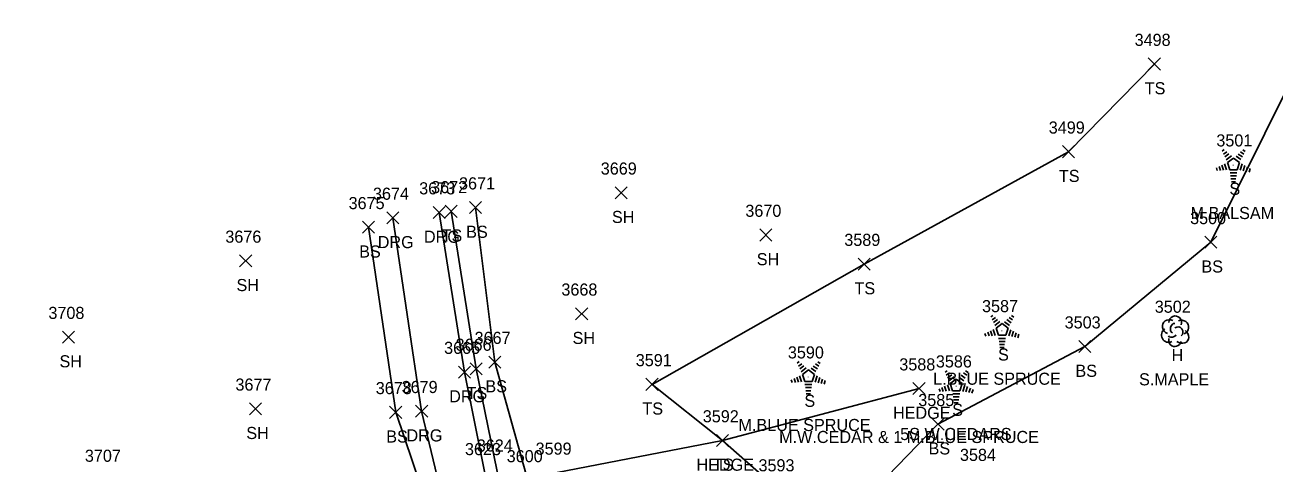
# Model space of a CAD drawing. Extents: x 1520648 to 1523413, y 732854 to 735518.
# Drawn here: x 1521334.6 to 1521541.1, y 733676.1 to 733748.5 of the extents above; entities that cross this region are included whole.
import ezdxf

# ---------------------------------------------------------------- set-up
doc = ezdxf.new("R2010")
doc.units = 0
for name, color, linetype in [('L_A', 7, 'Continuous'), ('L_C', 7, 'Continuous'), ('L_I', 7, 'Continuous'), ('L_TIC', 7, 'Continuous'), ('LAHR', 7, 'Continuous'), ('LELB', 7, 'Continuous'), ('LTC', 7, 'Continuous'), ('LTD', 7, 'Continuous'), ('R_A', 7, 'Continuous'), ('R_I', 7, 'Continuous'), ('R_TIC', 7, 'Continuous'), ('RDG', 7, 'Continuous')]:
    doc.layers.add(name, color=color, linetype=linetype)

msp = doc.modelspace()

# ---------------------------------------------------------------- linework, layer by layer
at = {"layer": 'L_TIC'}
for points in [[(1521520.34, 733741.06), (1521522.34, 733743.06)], [(1521522.34, 733741.06), (1521520.34, 733743.06)], [(1521506.15, 733726.57), (1521508.15, 733728.57)], [(1521508.15, 733726.57), (1521506.15, 733728.57)], [(1521432.17, 733719.79), (1521434.17, 733721.79)], [(1521434.17, 733719.79), (1521432.17, 733721.79)], [(1521404.08, 733716.72), (1521406.08, 733718.72)], [(1521406.08, 733716.72), (1521404.08, 733718.72)], [(1521408.12, 733717.34), (1521410.12, 733719.34)], [(1521410.12, 733717.34), (1521408.12, 733719.34)], [(1521390.43, 733714.08), (1521392.43, 733716.08)], [(1521392.43, 733714.08), (1521390.43, 733716.08)], [(1521456.11, 733712.81), (1521458.11, 733714.81)], [(1521458.11, 733712.81), (1521456.11, 733714.81)], [(1521529.67, 733711.6), (1521531.67, 733713.6)], [(1521531.67, 733711.6), (1521529.67, 733713.6)], [(1521370.11, 733708.53), (1521372.11, 733710.53)], [(1521372.11, 733708.53), (1521370.11, 733710.53)], [(1521472.35, 733708), (1521474.35, 733710)], [(1521474.35, 733708), (1521472.35, 733710)], [(1521425.66, 733699.79), (1521427.66, 733701.79)], [(1521427.66, 733699.79), (1521425.66, 733701.79)], [(1521340.83, 733695.93), (1521342.83, 733697.93)], [(1521342.83, 733695.93), (1521340.83, 733697.93)], [(1521508.85, 733694.36), (1521510.85, 733696.36)], [(1521510.85, 733694.36), (1521508.85, 733696.36)], [(1521408.22, 733690.67), (1521410.22, 733692.67)], [(1521410.22, 733690.67), (1521408.22, 733692.67)], [(1521411.3, 733691.8), (1521413.3, 733693.8)], [(1521413.3, 733691.8), (1521411.3, 733693.8)], [(1521437.29, 733688.12), (1521439.29, 733690.12)], [(1521439.29, 733688.12), (1521437.29, 733690.12)], [(1521481.43, 733687.42), (1521483.43, 733689.42)], [(1521483.43, 733687.42), (1521481.43, 733689.42)], [(1521371.72, 733684.08), (1521373.72, 733686.08)], [(1521373.72, 733684.08), (1521371.72, 733686.08)], [(1521394.91, 733683.5), (1521396.91, 733685.5)], [(1521396.91, 733683.5), (1521394.91, 733685.5)], [(1521484.57, 733681.53), (1521486.57, 733683.53)], [(1521486.57, 733681.53), (1521484.57, 733683.53)], [(1521448.94, 733678.84), (1521450.94, 733680.84)], [(1521450.94, 733678.84), (1521448.94, 733680.84)], [(1521448.94, 733678.84), (1521450.94, 733680.84)], [(1521450.94, 733678.84), (1521448.94, 733680.84)]]:
    msp.add_lwpolyline(points, dxfattribs=at)
at = {"layer": 'LAHR'}
msp.add_lwpolyline([(1521482.43, 733688.42), (1521449.94, 733679.84), (1521422.31, 733674.49)], dxfattribs=at)
at = {"layer": 'LELB'}
for points in [[(1521548.54, 733748.52), (1521530.67, 733712.6), (1521509.85, 733695.36), (1521485.57, 733682.53), (1521468.85, 733665.31), (1521458.55, 733648.55), (1521439.32, 733651.51), (1521417.73, 733673.25), (1521424.64, 733645.07), (1521433.28, 733636.36), (1521449.81, 733635.44), (1521465.25, 733627.96)], [(1521521.34, 733742.06), (1521507.15, 733727.57), (1521473.35, 733709), (1521438.29, 733689.12), (1521449.94, 733679.84), (1521459.15, 733671.74), (1521452.37, 733657.49), (1521440.03, 733660.34), (1521422.31, 733674.49)], [(1521685.16, 733676.19), (1521649.35, 733666.1), (1521610.03, 733655.91), (1521560.37, 733642.72), (1521505.12, 733628.18), (1521444.07, 733615.08), (1521437.41, 733615.5), (1521435.25, 733618.63), (1521426.81, 733622.91), (1521422.63, 733630.43), (1521418.08, 733649.02), (1521412.62, 733675.01), (1521409.22, 733691.67), (1521405.08, 733717.72)], [(1521417.73, 733673.25), (1521412.3, 733692.8), (1521409.12, 733718.34)], [(1521391.43, 733715.08), (1521395.91, 733684.5), (1521401.54, 733667.87), (1521402.17, 733661.87), (1521404.53, 733642.09), (1521399.77, 733626.22), (1521393.85, 733615.3), (1521389.77, 733604.49), (1521375.57, 733598.87), (1521346.27, 733591.74), (1521295.03, 733576.88), (1521253.17, 733566.96), (1521225.68, 733561.04), (1521193.61, 733550.49), (1521146.45, 733540.58), (1521095.03, 733527.62), (1521049.04, 733515.84), (1521035.57, 733513.93), (1521028.78, 733520.1), (1521023.54, 733528.05)]]:
    msp.add_lwpolyline(points, dxfattribs=at)
at = {"layer": 'LTC'}
for p, q in [((1521532.56, 733727.65), (1521532.91, 733727.91)), ((1521532.77, 733727.18), (1521533.3, 733727.57)), ((1521532.98, 733726.72), (1521533.68, 733727.23)), ((1521535.22, 733727.19), (1521535.9, 733726.7)), ((1521535.59, 733727.54), (1521536.14, 733727.14)), ((1521535.96, 733727.89), (1521536.38, 733727.59)), ((1521531.59, 733724.93), (1521531.74, 733724.46)), ((1521532.05, 733725.15), (1521532.26, 733724.49)), ((1521532.5, 733725.36), (1521532.77, 733724.53)), ((1521532.96, 733725.58), (1521533.29, 733724.56)), ((1521533.19, 733726.25), (1521534.07, 733726.89)), ((1521533.41, 733725.8), (1521534.43, 733726.53)), ((1521533.41, 733725.8), (1521533.8, 733724.6)), ((1521534.43, 733726.53), (1521535.42, 733725.81)), ((1521534.85, 733726.85), (1521535.65, 733726.26)), ((1521535.42, 733725.81), (1521535.03, 733724.6)), ((1521535.86, 733725.54), (1521535.52, 733724.5)), ((1521536.3, 733725.29), (1521536.02, 733724.4)), ((1521536.75, 733725.04), (1521536.51, 733724.31)), ((1521535.03, 733724.6), (1521533.8, 733724.6)), ((1521534.99, 733724.1), (1521533.85, 733724.1)), ((1521534.91, 733723.6), (1521533.92, 733723.6)), ((1521534.83, 733723.1), (1521533.99, 733723.1)), ((1521537.19, 733724.79), (1521537.01, 733724.21)), ((1521534.74, 733722.6), (1521534.07, 733722.6)), ((1521494.31, 733700.26), (1521494.66, 733700.52)), ((1521494.52, 733699.8), (1521495.05, 733700.18)), ((1521497.33, 733700.15), (1521497.88, 733699.76)), ((1521497.71, 733700.5), (1521498.13, 733700.2)), ((1521494.71, 733698.19), (1521495.04, 733697.17)), ((1521494.73, 733699.33), (1521495.43, 733699.84)), ((1521494.94, 733698.87), (1521495.81, 733699.5)), ((1521495.16, 733698.41), (1521496.17, 733699.15)), ((1521495.16, 733698.41), (1521495.55, 733697.22)), ((1521496.17, 733699.15), (1521497.17, 733698.42)), ((1521496.59, 733699.46), (1521497.4, 733698.87)), ((1521497.17, 733698.42), (1521496.78, 733697.22)), ((1521496.96, 733699.81), (1521497.64, 733699.31)), ((1521497.61, 733698.15), (1521497.27, 733697.11)), ((1521493.34, 733697.54), (1521493.49, 733697.07)), ((1521493.8, 733697.76), (1521494.01, 733697.11)), ((1521494.25, 733697.98), (1521494.52, 733697.14)), ((1521496.78, 733697.22), (1521495.55, 733697.22)), ((1521496.74, 733696.72), (1521495.6, 733696.72)), ((1521496.66, 733696.22), (1521495.67, 733696.22)), ((1521498.05, 733697.9), (1521497.76, 733697.01)), ((1521498.5, 733697.65), (1521498.26, 733696.92)), ((1521498.94, 733697.4), (1521498.75, 733696.82)), ((1521496.57, 733695.72), (1521495.74, 733695.72)), ((1521496.49, 733695.22), (1521495.81, 733695.22)), ((1521462.29, 733692.61), (1521462.64, 733692.87)), ((1521462.5, 733692.15), (1521463.03, 733692.53)), ((1521462.71, 733691.68), (1521463.41, 733692.19)), ((1521464.95, 733692.15), (1521465.63, 733691.66)), ((1521465.32, 733692.5), (1521465.87, 733692.1)), ((1521465.69, 733692.85), (1521466.11, 733692.55)), ((1521461.32, 733689.89), (1521461.47, 733689.42)), ((1521461.78, 733690.11), (1521461.99, 733689.45)), ((1521462.23, 733690.32), (1521462.5, 733689.49)), ((1521462.69, 733690.54), (1521463.02, 733689.52)), ((1521462.92, 733691.21), (1521463.8, 733691.85)), ((1521463.14, 733690.76), (1521464.16, 733691.49)), ((1521463.14, 733690.76), (1521463.53, 733689.57)), ((1521464.16, 733691.49), (1521465.15, 733690.77)), ((1521464.58, 733691.81), (1521465.38, 733691.22)), ((1521465.15, 733690.77), (1521464.76, 733689.57)), ((1521465.59, 733690.5), (1521465.25, 733689.46)), ((1521466.03, 733690.25), (1521465.75, 733689.36)), ((1521466.48, 733690), (1521466.24, 733689.27)), ((1521486.73, 733691.11), (1521487.08, 733691.37)), ((1521486.94, 733690.65), (1521487.47, 733691.03)), ((1521487.15, 733690.18), (1521487.85, 733690.69)), ((1521487.36, 733689.72), (1521488.24, 733690.35)), ((1521487.58, 733689.26), (1521488.59, 733690)), ((1521488.59, 733690), (1521489.59, 733689.27)), ((1521489.01, 733690.31), (1521489.82, 733689.72)), ((1521489.39, 733690.66), (1521490.06, 733690.16)), ((1521489.76, 733691.01), (1521490.31, 733690.61)), ((1521490.13, 733691.35), (1521490.55, 733691.05)), ((1521464.76, 733689.57), (1521463.53, 733689.57)), ((1521464.72, 733689.07), (1521463.58, 733689.07)), ((1521464.64, 733688.57), (1521463.65, 733688.57)), ((1521464.56, 733688.07), (1521463.72, 733688.07)), ((1521466.92, 733689.75), (1521466.74, 733689.17)), ((1521485.76, 733688.39), (1521485.91, 733687.92)), ((1521486.22, 733688.61), (1521486.43, 733687.96)), ((1521486.67, 733688.83), (1521486.94, 733687.99)), ((1521487.13, 733689.04), (1521487.46, 733688.02)), ((1521487.58, 733689.26), (1521487.97, 733688.07)), ((1521489.2, 733688.07), (1521487.97, 733688.07)), ((1521489.59, 733689.27), (1521489.2, 733688.07)), ((1521490.03, 733689), (1521489.69, 733687.96)), ((1521490.47, 733688.75), (1521490.19, 733687.86)), ((1521490.92, 733688.5), (1521490.68, 733687.77)), ((1521491.36, 733688.25), (1521491.18, 733687.67)), ((1521464.47, 733687.57), (1521463.8, 733687.57)), ((1521489.16, 733687.57), (1521488.02, 733687.57)), ((1521489.08, 733687.07), (1521488.09, 733687.07)), ((1521488.99, 733686.57), (1521488.16, 733686.57)), ((1521488.91, 733686.07), (1521488.24, 733686.07))]:
    msp.add_line(p, q, dxfattribs=at)
at = {"layer": 'LTD'}
msp.add_line((1521524.75, 733697.95), (1521524.75, 733697.95), dxfattribs=at)
msp.add_line((1521524.75, 733697.95), (1521524.75, 733697.95), dxfattribs=at)
msp.add_arc((1521524.8, 733699.38), 1.05, 335.5272, 180.9563, dxfattribs=at)
for centre, major_axis, ratio, start_param, end_param in [((1521523.67, 733697.24), (0.58, -1.04), 0.959034, 3.141593, 6.283185), ((1521523.96, 733698.61), (1.21, -0.51), 0.895232, 1.570796, 4.712389), ((1521524.54, 733698.41), (-0.208, -0.792), 0.645439, 3.141593, 6.283185), ((1521525.25, 733697.78), (-0.5, 0.667), 0.989748, 3.141593, 6.283185), ((1521525.79, 733698.53), (-1.14, -0.48), 0.949671, 1.570796, 4.712389), ((1521524.75, 733696.45), (0.26, 1.06), 0.942809, 1.570796, 4.712389), ((1521524.29, 733697.2), (-0.625, -0.083), 0.423636, 0, 3.141593), ((1521525.75, 733697.11), (-1.09, 0.79), 0.841452, 1.570796, 4.712389)]:
    msp.add_ellipse(centre, major_axis=major_axis, ratio=ratio, start_param=start_param, end_param=end_param, dxfattribs=at)
at = {"layer": 'R_TIC'}
for points in [[(1521394.45, 733715.63), (1521396.45, 733717.63)], [(1521396.45, 733715.63), (1521394.45, 733717.63)], [(1521402.1, 733716.52), (1521404.1, 733718.52)], [(1521404.1, 733716.52), (1521402.1, 733718.52)], [(1521406.27, 733690.15), (1521408.27, 733692.15)], [(1521408.27, 733690.15), (1521406.27, 733692.15)], [(1521399.2, 733683.68), (1521401.2, 733685.68)], [(1521401.2, 733683.68), (1521399.2, 733685.68)]]:
    msp.add_lwpolyline(points, dxfattribs=at)
at = {"layer": 'RDG'}
for points in [[(1521435.97, 733610.22), (1521429.03, 733615.22), (1521422.83, 733621.99), (1521420.09, 733628.28), (1521415.86, 733648.78), (1521410.67, 733674.42), (1521407.27, 733691.15), (1521403.1, 733717.52)], [(1521395.45, 733716.63), (1521400.2, 733684.68), (1521404.03, 733668.62), (1521408.35, 733642.84), (1521411.24, 733624.83), (1521410.44, 733612.16), (1521404.4, 733607.55), (1521391.63, 733601.72), (1521385.65, 733597.39)]]:
    msp.add_lwpolyline(points, dxfattribs=at)

# ---------------------------------------------------------------- texts
at = {"layer": 'L_A'}
for s, p in [('TS', (1521519.75, 733737.06)), ('TS', (1521505.56, 733722.57)), ('S', (1521533.75, 733720.44)), ('SH', (1521431.66, 733715.79)), ('TS', (1521403.49, 733712.72)), ('BS', (1521407.56, 733713.34)), ('BS', (1521389.87, 733710.08)), ('SH', (1521455.6, 733708.81)), ('BS', (1521529.12, 733707.6)), ('SH', (1521369.59, 733704.53)), ('TS', (1521471.76, 733704)), ('SH', (1521425.15, 733695.79)), ('SH', (1521340.32, 733691.93)), ('S', (1521495.5, 733693.05)), ('H', (1521524.18, 733692.95)), ('BS', (1521508.29, 733690.36)), ('BS', (1521410.74, 733687.8)), ('TS', (1521407.63, 733686.67)), ('TS', (1521436.7, 733684.12)), ('S', (1521463.48, 733685.4)), ('S', (1521487.92, 733683.91)), ('HEDGE', (1521478.13, 733683.42)), ('SH', (1521371.21, 733680.08)), ('BS', (1521394.35, 733679.5)), ('BS', (1521484.01, 733677.53)), ('HEDGE', (1521445.64, 733674.84)), ('TS', (1521448.35, 733674.84))]:
    msp.add_text(s, height=2, dxfattribs=at).set_placement(p)
at = {"layer": 'L_C'}
for s, p in [('M.BALSAM', (1521527.33, 733716.44)), ('L.BLUE SPRUCE', (1521484.77, 733689.05)), ('S.MAPLE', (1521518.81, 733688.95)), ('M.BLUE SPRUCE', (1521452.58, 733681.4)), ('5S.W.CEDARS', (1521479.32, 733679.91)), ('M.W.CEDAR & 1 M.BLUE SPRUCE', (1521459.31, 733679.42))]:
    msp.add_text(s, height=2, dxfattribs=at).set_placement(p)
at = {"layer": 'L_I'}
for s, p in [('3498', (1521518.08, 733745.06)), ('3499', (1521503.88, 733730.57)), ('3501', (1521531.59, 733728.44)), ('3669', (1521429.81, 733723.79)), ('3671', (1521406.38, 733721.34)), ('3672', (1521401.77, 733720.72)), ('3675', (1521388.12, 733718.08)), ('3670', (1521453.72, 733716.81)), ('3500', (1521527.25, 733715.6)), ('3676', (1521367.74, 733712.53)), ('3589', (1521470.08, 733712)), ('3668', (1521423.3, 733703.79)), ('3587', (1521492.85, 733701.05)), ('3502', (1521521.41, 733700.95)), ('3708', (1521338.49, 733699.93)), ('3503', (1521506.51, 733698.36)), ('3666', (1521405.81, 733694.67)), ('3667', (1521408.95, 733695.8)), ('3591', (1521435.6, 733692.12)), ('3590', (1521460.75, 733693.4)), ('3586', (1521485.22, 733691.91)), ('3588', (1521479.17, 733691.42)), ('3677', (1521369.41, 733688.08)), ('3678', (1521392.61, 733687.5)), ('3585', (1521482.31, 733685.53)), ('3592', (1521446.68, 733682.84)), ('3592', (1521446.68, 733682.84)), ('3624', (1521409.31, 733678.01)), ('3599', (1521419.04, 733677.49)), ('3599', (1521419.04, 733677.49)), ('3707', (1521344.52, 733676.32)), ('3600', (1521414.26, 733676.25)), ('3600', (1521414.26, 733676.25)), ('3584', (1521489.2, 733676.46)), ('3593', (1521455.89, 733674.74))]:
    msp.add_text(s, height=2, dxfattribs=at).set_placement(p)
at = {"layer": 'LTC'}
for p in [(1521534.31, 733725.55), (1521496.06, 733698.16), (1521464.04, 733690.51), (1521488.48, 733689.01)]:
    msp.add_text('.', height=1.04, rotation=270, dxfattribs=at).set_placement(p)
at = {"layer": 'R_A'}
for p in [(1521392.94, 733711.63), (1521400.58, 733712.52), (1521404.75, 733686.15), (1521397.69, 733679.68)]:
    msp.add_text('DRG', height=2, dxfattribs=at).set_placement(p)
at = {"layer": 'R_I'}
for s, p in [('3674', (1521392.15, 733719.63)), ('3673', (1521399.79, 733720.52)), ('3665', (1521403.91, 733694.15)), ('3679', (1521396.89, 733687.68)), ('3623', (1521407.36, 733677.42))]:
    msp.add_text(s, height=2, dxfattribs=at).set_placement(p)

doc.saveas('drawing.dxf')
